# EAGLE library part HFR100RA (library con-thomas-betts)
THOMAS&BETTS
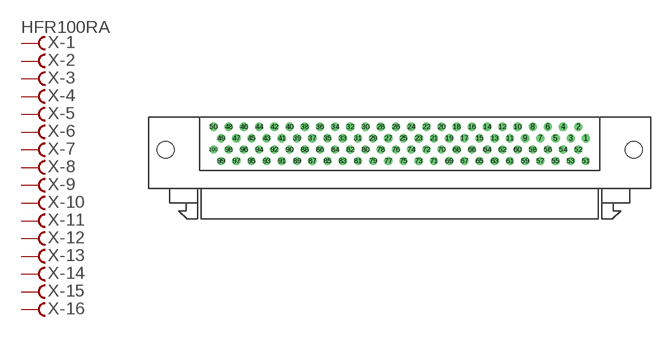
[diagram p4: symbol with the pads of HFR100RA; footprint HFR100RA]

Designator prefix X; gates -1=FV -2=F -3=F -4=F -5=F -6=F -7=F -8=F -9=F -10=F -11=F -12=F -13=F -14=F -15=F -16=F -17=F -18=F -19=F -20=F -21=F -22=F -23=F -24=F -25=F -27=F -28=F -29=F -30=F -31=F -32=F -33=F -34=F -35=F -36=F -37=F -38=F -39=F -40=F -41=F -42=F -43=F -44=F -45=F -46=F -47=F -48=F -49=F -50=F -52=F -53=F -54=F -55=F -56=F -57=F -58=F -59=F -60=F -61=F -62=F -63=F -64=F -65=F -66=F -67=F -68=F -69=F -70=F -71=F -72=F -73=F -74=F -75=F -77=F -78=F -79=F -80=F -81=F -82=F -83=F -84=F -85=F -86=F -87=F -88=F -89=F -90=F -91=F -92=F -93=F -94=F -95=F -96=F -97=F -98=F -99=F -100=F -26=F -51=F -76=F

## HFR100RA  [HFR100RA]
1  -1:F  pas
2  -2:F  pas
3  -3:F  pas
4  -4:F  pas
5  -5:F  pas
6  -6:F  pas
7  -7:F  pas
8  -8:F  pas
9  -9:F  pas
10  -10:F  pas
11  -11:F  pas
12  -12:F  pas
13  -13:F  pas
14  -14:F  pas
15  -15:F  pas
16  -16:F  pas
17  -17:F  pas
18  -18:F  pas
19  -19:F  pas
20  -20:F  pas
21  -21:F  pas
22  -22:F  pas
23  -23:F  pas
24  -24:F  pas
25  -25:F  pas
26  -26:F  pas
27  -27:F  pas
28  -28:F  pas
29  -29:F  pas
30  -30:F  pas
31  -31:F  pas
32  -32:F  pas
33  -33:F  pas
34  -34:F  pas
35  -35:F  pas
36  -36:F  pas
37  -37:F  pas
38  -38:F  pas
39  -39:F  pas
40  -40:F  pas
41  -41:F  pas
42  -42:F  pas
43  -43:F  pas
44  -44:F  pas
45  -45:F  pas
46  -46:F  pas
47  -47:F  pas
48  -48:F  pas
49  -49:F  pas
50  -50:F  pas
51  -51:F  pas
52  -52:F  pas
53  -53:F  pas
54  -54:F  pas
55  -55:F  pas
56  -56:F  pas
57  -57:F  pas
58  -58:F  pas
59  -59:F  pas
60  -60:F  pas
61  -61:F  pas
62  -62:F  pas
63  -63:F  pas
64  -64:F  pas
65  -65:F  pas
66  -66:F  pas
67  -67:F  pas
68  -68:F  pas
69  -69:F  pas
70  -70:F  pas
71  -71:F  pas
72  -72:F  pas
73  -73:F  pas
74  -74:F  pas
75  -75:F  pas
76  -76:F  pas
77  -77:F  pas
78  -78:F  pas
79  -79:F  pas
80  -80:F  pas
81  -81:F  pas
82  -82:F  pas
83  -83:F  pas
84  -84:F  pas
85  -85:F  pas
86  -86:F  pas
87  -87:F  pas
88  -88:F  pas
89  -89:F  pas
90  -90:F  pas
91  -91:F  pas
92  -92:F  pas
93  -93:F  pas
94  -94:F  pas
95  -95:F  pas
96  -96:F  pas
97  -97:F  pas
98  -98:F  pas
99  -99:F  pas
100  -100:F  pas

## Footprint HFR100RA (pad centres in mm)
THOMAS&BETTS
drill 0.864 octagon: 1 31.115,6.985
drill 0.864 round: 2 29.845,8.89; 3 28.575,6.985; 4 27.305,8.89; 5 26.035,6.985; 6 24.765,8.89; 7 23.495,6.985; 8 22.225,8.89; 9 20.955,6.985; 10 19.685,8.89; 11 18.415,6.985; 12 17.145,8.89; 13 15.875,6.985; 14 14.605,8.89; 15 13.335,6.985; 16 12.065,8.89; 17 10.795,6.985; 18 9.525,8.89; 19 8.255,6.985; 20 6.985,8.89; 21 5.715,6.985; 22 4.445,8.89; 23 3.175,6.985; 24 1.905,8.89; 25 0.635,6.985; 26 -0.635,8.89; 27 -1.905,6.985; 28 -3.175,8.89; 29 -4.445,6.985; 30 -5.715,8.89; 31 -6.985,6.985; 32 -8.255,8.89; 33 -9.525,6.985; 34 -10.795,8.89; 35 -12.065,6.985; 36 -13.335,8.89; 37 -14.605,6.985; 38 -15.875,8.89; 39 -17.145,6.985; 40 -18.415,8.89; 41 -19.685,6.985; 42 -20.955,8.89; 43 -22.225,6.985; 44 -23.495,8.89; 45 -24.765,6.985; 46 -26.035,8.89; 47 -27.305,6.985; 48 -28.575,8.89; 49 -29.845,6.985; 50 -31.115,8.89; 51 31.115,3.175; 52 29.845,5.08; 53 28.575,3.175; 54 27.305,5.08; 55 26.035,3.175; 56 24.765,5.08; 57 23.495,3.175; 58 22.225,5.08; 59 20.955,3.175; 60 19.685,5.08; 61 18.415,3.175; 62 17.145,5.08; 63 15.875,3.175; 64 14.605,5.08; 65 13.335,3.175; 66 12.065,5.08; 67 10.795,3.175; 68 9.525,5.08; 69 8.255,3.175; 70 6.985,5.08; 71 5.715,3.175; 72 4.445,5.08; 73 3.175,3.175; 74 1.905,5.08; 75 0.635,3.175; 76 -0.635,5.08; 77 -1.905,3.175; 78 -3.175,5.08; 79 -4.445,3.175; 80 -5.715,5.08; 81 -6.985,3.175; 82 -8.255,5.08; 83 -9.525,3.175; 84 -10.795,5.08; 85 -12.065,3.175; 86 -13.335,5.08; 87 -14.605,3.175; 88 -15.875,5.08; 89 -17.145,3.175; 90 -18.415,5.08; 91 -19.685,3.175; 92 -20.955,5.08; 93 -22.225,3.175; 94 -23.495,5.08; 95 -24.765,3.175; 96 -26.035,5.08; 97 -27.305,3.175; 98 -28.575,5.08; 99 -29.845,3.175; 100 -31.115,5.08
hole 2.769 at 39.116,5.08
hole 2.769 at -39.116,5.08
